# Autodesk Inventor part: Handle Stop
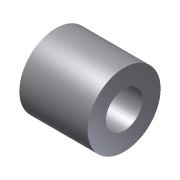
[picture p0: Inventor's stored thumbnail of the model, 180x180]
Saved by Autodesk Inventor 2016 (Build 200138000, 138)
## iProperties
Shininess: 77.0
Length Units: 11269
Angle Units: 11279
Time Units: 11290
Mass Units: 11283
Length Display Precision: 3
Angle Display Precision: 2
Compacted: True
Created: 2002-02
Part Number: Handle Stop
Document SubType Name: Modeling
Designer: ***
Density: 1 g/cm^3
Material: Generic
Appearance: Default
Density: 0.0
Volumn: 0.0
Area: 0.0
PropertySet Name: Model Information
Control State: 0
Master: False
Checked Out: False
Author: ***
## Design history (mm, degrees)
sketch "Sketch1"
  geometry: L1 (0, 0)-(0, -2); L2 (0, -2)-(8, -2); L3 (8, -2)-(8, 13); L4 (8, 13)-(4, 13); L5 (4, 13)-(4, 0); L6 (4, 0)-(0, 0)
  constraints: 12 end point, 4 parallel, 1 perpendicular, 1 vertical
  dimensions: "d0" = 16 diameter of L3 L1; "d1" = 8 diameter of L5 L1; "d2" = 2 distance of L1.start L1.end; "d3" = 15 distance of L2.end L3.end
revolve "Revolution1" sketch "Sketch1" stored, may be unused: angle "d4" = 90 deg
body "Solid1"
